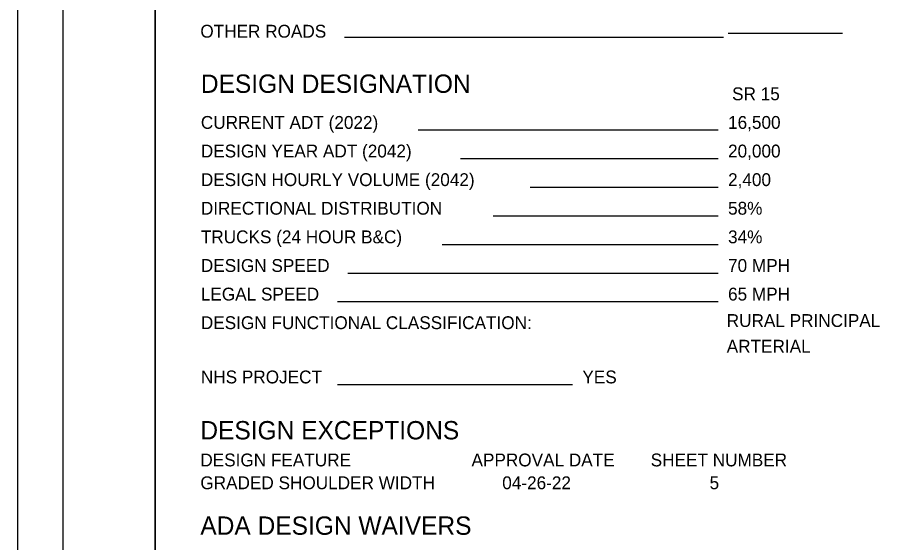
# Model space of a CAD drawing. Extents: x 0 to 45.5, y 0 to 22.
# Drawn here: x 0 to 9.53, y 5.37 to 11.1 of the extents above; entities that cross this region are included whole.
import ezdxf

# ---------------------------------------------------------------- set-up
doc = ezdxf.new("R2010")
doc.units = 0
for name, color, linetype in [('SH_Border', 7, 'Continuous'), ('SH_Cut_Line', 7, 'Continuous'), ('SH_Data', 7, 'Continuous'), ('SH_Text', 7, 'Continuous')]:
    doc.layers.add(name, color=color, linetype=linetype)

msp = doc.modelspace()

# ---------------------------------------------------------------- linework, layer by layer
at = {"layer": 'SH_Border'}
for points in [[(0.5, 21.5), (1.5, 21.5), (1.5, 0.5), (0.5, 0.5)], [(1.5, 21.5), (33.5, 21.5), (33.5, 0.5), (1.5, 0.5)]]:
    msp.add_lwpolyline(points, close=True, dxfattribs=at)
at = {"layer": 'SH_Cut_Line'}
msp.add_lwpolyline([(0, 0), (34, 0), (34, 22), (0, 22)], close=True, dxfattribs=at)
at = {"layer": 'SH_Data'}
for p, q in [((7.7, 10.8767), (3.5657, 10.8767)), ((9, 10.9223), (7.75, 10.9223)), ((7.6424, 9.8662), (4.3704, 9.8662)), ((7.6424, 9.5542), (4.8302, 9.5542)), ((7.6424, 9.2422), (5.5912, 9.2422)), ((7.6424, 8.9302), (5.1869, 8.9302)), ((7.6424, 8.6182), (4.632, 8.6182)), ((7.6424, 8.3062), (3.6014, 8.3062)), ((7.6424, 7.9942), (3.4886, 7.9942)), ((6.0532, 7.0905), (3.4886, 7.0905))]:
    msp.add_line(p, q, dxfattribs=at)

# ---------------------------------------------------------------- texts
for s, height, p in [('OTHER ROADS', 0.14, (1.9944, 10.8767)), ('DESIGN DESIGNATION', 0.2, (2, 10.2747)), ('CURRENT ADT (2022)', 0.14, (2, 9.8822)), ('16,500', 0.14, (7.75, 9.8822)), ('DESIGN YEAR ADT (2042)', 0.14, (2, 9.5702)), ('20,000', 0.14, (7.75, 9.5702)), ('DESIGN HOURLY VOLUME (2042)', 0.14, (2, 9.2582)), ('2,400', 0.14, (7.75, 9.2582)), ('DIRECTIONAL DISTRIBUTION', 0.14, (2, 8.9462)), ('58%', 0.14, (7.75, 8.9462)), ('TRUCKS (24 HOUR B&C)', 0.14, (2, 8.6342)), ('34%', 0.14, (7.75, 8.6342)), ('DESIGN SPEED', 0.14, (2, 8.3221)), ('70 MPH', 0.14, (7.75, 8.3221)), ('LEGAL SPEED', 0.14, (2, 8.0101)), ('65 MPH', 0.14, (7.75, 8.0101)), ('DESIGN FUNCTIONAL CLASSIFICATION:', 0.14, (2, 7.6981)), ('RURAL PRINCIPAL', 0.14, (7.7354, 7.7214)), ('ARTERIAL', 0.14, (7.7354, 7.4414)), ('NHS PROJECT', 0.14, (2, 7.1063)), ('YES', 0.14, (6.1608, 7.1063)), ('DESIGN EXCEPTIONS', 0.2, (1.9944, 6.4954)), ('DESIGN FEATURE', 0.14, (1.9944, 6.201)), ('APPROVAL DATE', 0.14, (4.9522, 6.201)), ('SHEET NUMBER', 0.14, (6.9064, 6.201)), ('GRADED SHOULDER WIDTH', 0.14, (1.9944, 5.9522)), ('04-26-22', 0.14, (5.2872, 5.9522)), ('5', 0.14, (7.5485, 5.9522)), ('ADA DESIGN WAIVERS', 0.2, (1.9944, 5.4551))]:
    msp.add_text(s, height=height, dxfattribs=at).set_placement(p)
at = {"layer": 'SH_Text'}
msp.add_text('SR 15', height=0.14, dxfattribs=at).set_placement((7.7939, 10.1942))

doc.saveas('drawing.dxf')
